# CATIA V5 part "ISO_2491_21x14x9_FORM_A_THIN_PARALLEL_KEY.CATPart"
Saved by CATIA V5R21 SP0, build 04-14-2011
Part number: ISO 2491 KEY 22x5x3 THIN PARALLEL FORM A
Publications: "Mating Face", "Axis"
Bounding box of the stored display mesh (mm): x 0 to 9, y -7 to 13.824, z -7 to 7
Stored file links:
  C:\Users\MIRCEA\Desktop\MOM\Mogan\model\ISO_2491_21x14x9_FORM_A_THIN_PARALLEL_KEY.CATPart
  C:\Program Files (x86)\Dassault Systemes\B21\intel_a\startup\components\MechanicalStandardParts\ISO_Standards\Design_Tables\ISO_2491_THIN_PARALLEL_KEY_FORM_A.txt
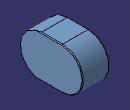
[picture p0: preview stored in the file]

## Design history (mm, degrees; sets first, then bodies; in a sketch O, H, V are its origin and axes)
Parameters
  l_length = 21 mm
  b_width = 14 mm
  h_thickness = 9 mm
  s_chamfer_min = 0.25 mm
  s_chamfer_max = 0.4 mm
  `Part Name` = "ISO 2491 KEY 14x6x4 THIN PARALLEL FORM A"
  `Part Number` = "ISO_2491_14x6x4_THIN_PARALLEL_KEY_FORM_A"
  PartName = "ISO_2491_22x5x3_FORM_A_THIN_PARALLEL_KEY"
  PartNumber = "ISO 2491 KEY 22x5x3 THIN PARALLEL FORM A"
Body1 "PartBody" (main body)
  Sketch1 on yz-plane, origin (0, 0, 0), H (0, 1, 0), V (0, 0, 1)
    line L1 (0, -7) -> (7, -7)
    arc A1 centre (7, 0) radius 7 from (7, -7) to (7, 7) ccw
    line L2 (7, 7) -> (0, 7)
    point P5 (0, 7)
    arc A2 centre (0, 0) radius 7 from (0, 7) to (0, -7) ccw
    point P6 (0, 0)
    radius A1 = 7 {= ( b_width * .5)}
    distance P5 H = 7 {= b_width /2}
    distance A2 A1 = 21 {= l_length}
    radius A2 = 7 {= ( b_width * .5)}
    tangency: A1 L1, L2 A1, A2 L2, L1 A2
    horizontal: L2 H
    coincidence: P6 V
  Pad1: profile Sketch1, direction (1, 0, 0), length 9 {= h_thickness}
  Chamfer1: length 0.25 {= s_chamfer_min}, angle 45, on edge [face of Pad1 | face of Pad1]
  Chamfer2: length 0.25 {= s_chamfer_min}, angle 45, on face of Pad1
